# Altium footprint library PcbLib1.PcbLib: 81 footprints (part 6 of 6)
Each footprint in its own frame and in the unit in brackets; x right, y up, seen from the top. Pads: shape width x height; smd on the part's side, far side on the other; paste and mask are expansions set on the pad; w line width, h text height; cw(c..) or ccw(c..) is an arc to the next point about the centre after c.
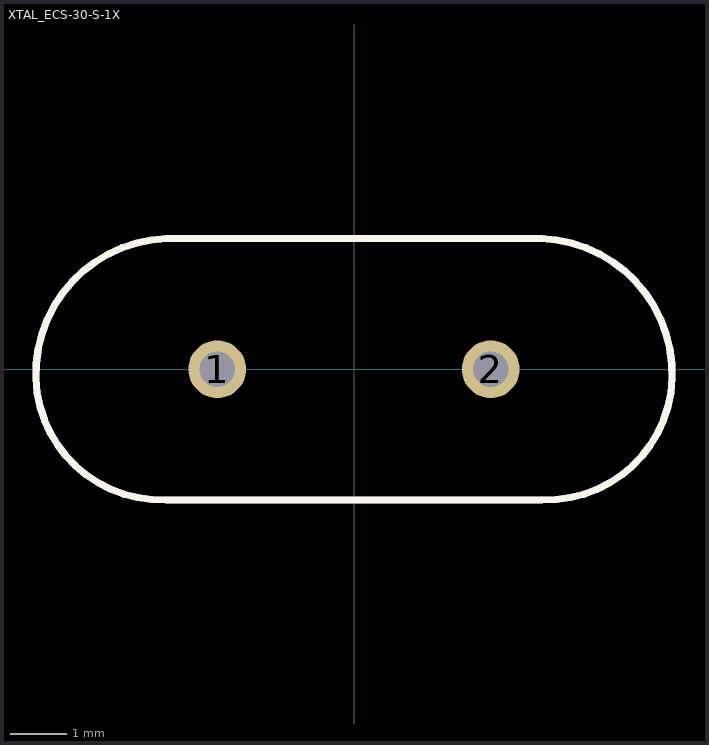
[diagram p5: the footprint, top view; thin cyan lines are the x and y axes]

## XTAL_ECS-30-S-1X [mm]
pads (2):
  round 1.03 hole 0.63: 1(-2.44,0) 2(2.44,0)
Top Overlay:
  lines w0.127: -5.675,-0.169 cw(c-3.26,-0.085) -3.344,2.33 ; -5.675,-0.168 ccw(c-3.435,-0.09) -3.357,-2.33 ; -3.35,-2.33 3.35,-2.33 ; -3.35,2.33 3.35,2.33 ; 3.344,2.33 cw(c3.26,-0.085) 5.675,-0.169 ; 3.357,-2.33 ccw(c3.435,-0.09) 5.675,-0.168
Mechanical 13:
  lines w0.127: -5.675,-0.169 cw(c-3.26,-0.085) -3.344,2.33 ; -5.675,-0.168 ccw(c-3.435,-0.09) -3.357,-2.33 ; -3.35,-2.33 3.35,-2.33 ; -3.35,2.33 3.35,2.33 ; 3.344,2.33 cw(c3.26,-0.085) 5.675,-0.169 ; 3.357,-2.33 ccw(c3.435,-0.09) 5.675,-0.168
3D body "ECS-121-S-4X 12.096.STEP": height 3.5, standoff -12.7, extent -5.7,-2.25 5.65,2.4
